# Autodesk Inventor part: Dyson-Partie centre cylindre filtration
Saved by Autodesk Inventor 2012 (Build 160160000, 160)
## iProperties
Created: 2012-11
Part Number: Dyson-Partie centre cylindre filtration
Material: Default
Document SubType Name: Modeling
Designer: Administrateur
Density: 1 g/cm^3
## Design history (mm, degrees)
node "Dyson-Partie centre cylindre filtration1"
node "Dyson-Partie centre cylindre filtration"
node "Base1"
